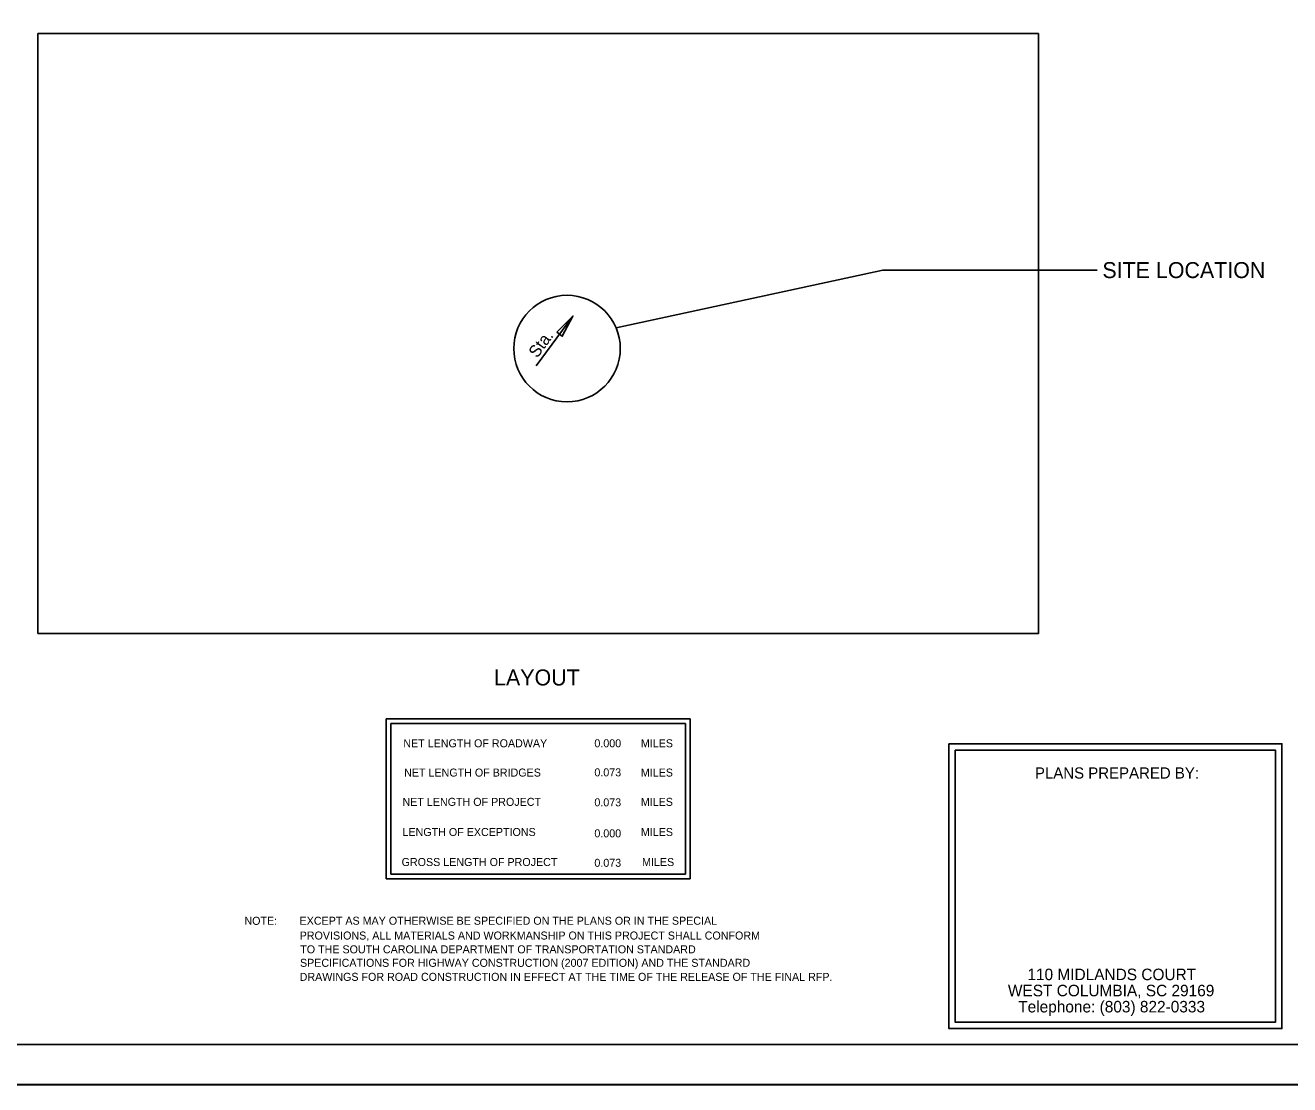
# Model space of a CAD drawing. Extents: x -1142 to 658, y -589 to 511.
# Drawn here: x -534 to 256, y -589 to 73 of the extents above; entities that cross this region are included whole.
import ezdxf

# ---------------------------------------------------------------- set-up
doc = ezdxf.new("R2010")
doc.units = 0
for name, color, linetype in [('BR_BORDER LINES', 7, 'Continuous'), ('BR_REBAR', 7, 'Continuous'), ('Default', 7, 'Continuous'), ('Level 31', 7, 'Continuous'), ('RD_SHT_IplotShp', 7, 'Continuous')]:
    doc.layers.add(name, color=color, linetype=linetype)

msp = doc.modelspace()

# ---------------------------------------------------------------- linework, layer by layer
at = {"layer": 'BR_BORDER LINES'}
msp.add_line((-1041.79, -564.26), (633.21, -564.26), dxfattribs=at)
at = {"layer": 'BR_REBAR'}
for p, q in [((1.78, -80.34), (-164.81, -116.39)), ((1.78, -80.34), (135.59, -80.34)), ((-214.86, -140.13), (-191.84, -109))]:
    msp.add_line(p, q, dxfattribs=at)
msp.add_lwpolyline([(-201.89, -119.05), (-191.84, -109), (-198.5, -121.56)], close=True, dxfattribs=at)
msp.add_circle((-195.49, -129.28), 33.27, dxfattribs=at)
at = {"layer": 'Default'}
for p, q in [((-118.53, -360.66), (-308.53, -360.66)), ((-308.53, -360.66), (-308.53, -460.66)), ((-118.53, -460.66), (-118.53, -360.66)), ((-121.53, -363.66), (-305.53, -363.66)), ((-305.53, -363.66), (-305.53, -457.71)), ((-121.53, -457.71), (-121.53, -363.66)), ((-305.48, -457.66), (-121.53, -457.66)), ((-308.53, -460.66), (-118.53, -460.66))]:
    msp.add_line(p, q, dxfattribs=at)
for points in [[(-526.03, -307.45), (98.97, -307.45), (98.97, 67.55), (-526.03, 67.55)], [(43.05, -376.26), (251.05, -376.26), (251.05, -554.26), (43.05, -554.26)], [(47.05, -380.26), (247.05, -380.26), (247.05, -550.26), (47.05, -550.26)]]:
    msp.add_lwpolyline(points, close=True, dxfattribs=at)
at = {"layer": 'Level 31'}
msp.add_lwpolyline([(-1141.79, 510.67), (-1141.79, -589.33), (658.21, -589.33), (658.21, 510.67)], dxfattribs=at)
at = {"layer": 'RD_SHT_IplotShp'}
msp.add_line((-1141.79, -589.26), (658.21, -589.26), dxfattribs=at)

# ---------------------------------------------------------------- texts
at = {"layer": 'BR_REBAR'}
msp.add_text('Sta.', height=7.5, rotation=53.74705, dxfattribs=at).set_placement((-214.12, -135.64))
at = {"layer": 'Default'}
for s, height, p in [('SITE LOCATION', 10, (138.93, -85.26)), ('LAYOUT', 10, (-241.07, -339.83)), ('NET LENGTH OF ROADWAY', 5.0001, (-297.78, -378.46)), ('0.000', 5, (-178.41, -378.46)), ('MILES', 5, (-149.38, -378.46)), ('NET LENGTH OF BRIDGES', 5.0001, (-297.28, -396.76)), ('0.073', 5, (-178.41, -396.63)), ('MILES', 5, (-149.39, -396.76)), ('PLANS PREPARED BY:', 7, (96.8, -398.01)), ('NET LENGTH OF PROJECT', 5.0001, (-298.28, -415.06)), ('0.073', 5, (-178.41, -415.36)), ('MILES', 5, (-149.4, -415.06)), ('LENGTH OF EXCEPTIONS', 5.0001, (-298.28, -433.91)), ('0.000', 5, (-178.41, -434.73)), ('MILES', 5, (-149.37, -433.91)), ('GROSS LENGTH OF PROJECT', 5.0001, (-298.83, -452.66)), ('0.073', 5, (-178.41, -453.14)), ('MILES', 5, (-148.63, -452.66)), ('NOTE:', 5, (-397.02, -489.41)), ('EXCEPT AS MAY OTHERWISE BE SPECIFIED ON THE PLANS OR IN THE SPECIAL ', 5.0001, (-362.56, -489.35)), ('PROVISIONS, ALL MATERIALS AND WORKMANSHIP ON THIS PROJECT SHALL CONFORM ', 5.0001, (-362.51, -498.6)), ('TO THE SOUTH CAROLINA DEPARTMENT OF TRANSPORTATION STANDARD ', 5.0001, (-362.15, -507.22)), ('SPECIFICATIONS FOR HIGHWAY CONSTRUCTION (2007 EDITION) AND THE STANDARD', 5.0001, (-362.31, -515.65)), ('DRAWINGS FOR ROAD CONSTRUCTION IN EFFECT AT THE TIME OF THE RELEASE OF THE FINAL RFP.', 5.0001, (-362.53, -524.42)), ('110 MIDLANDS COURT', 7.2, (92.09, -523.99)), ('WEST COLUMBIA, SC 29169', 7.2, (79.91, -534.07)), ('Telephone: (803) 822-0333', 7.2, (86.35, -544.15))]:
    msp.add_text(s, height=height, dxfattribs=at).set_placement(p)

doc.saveas('drawing.dxf')
